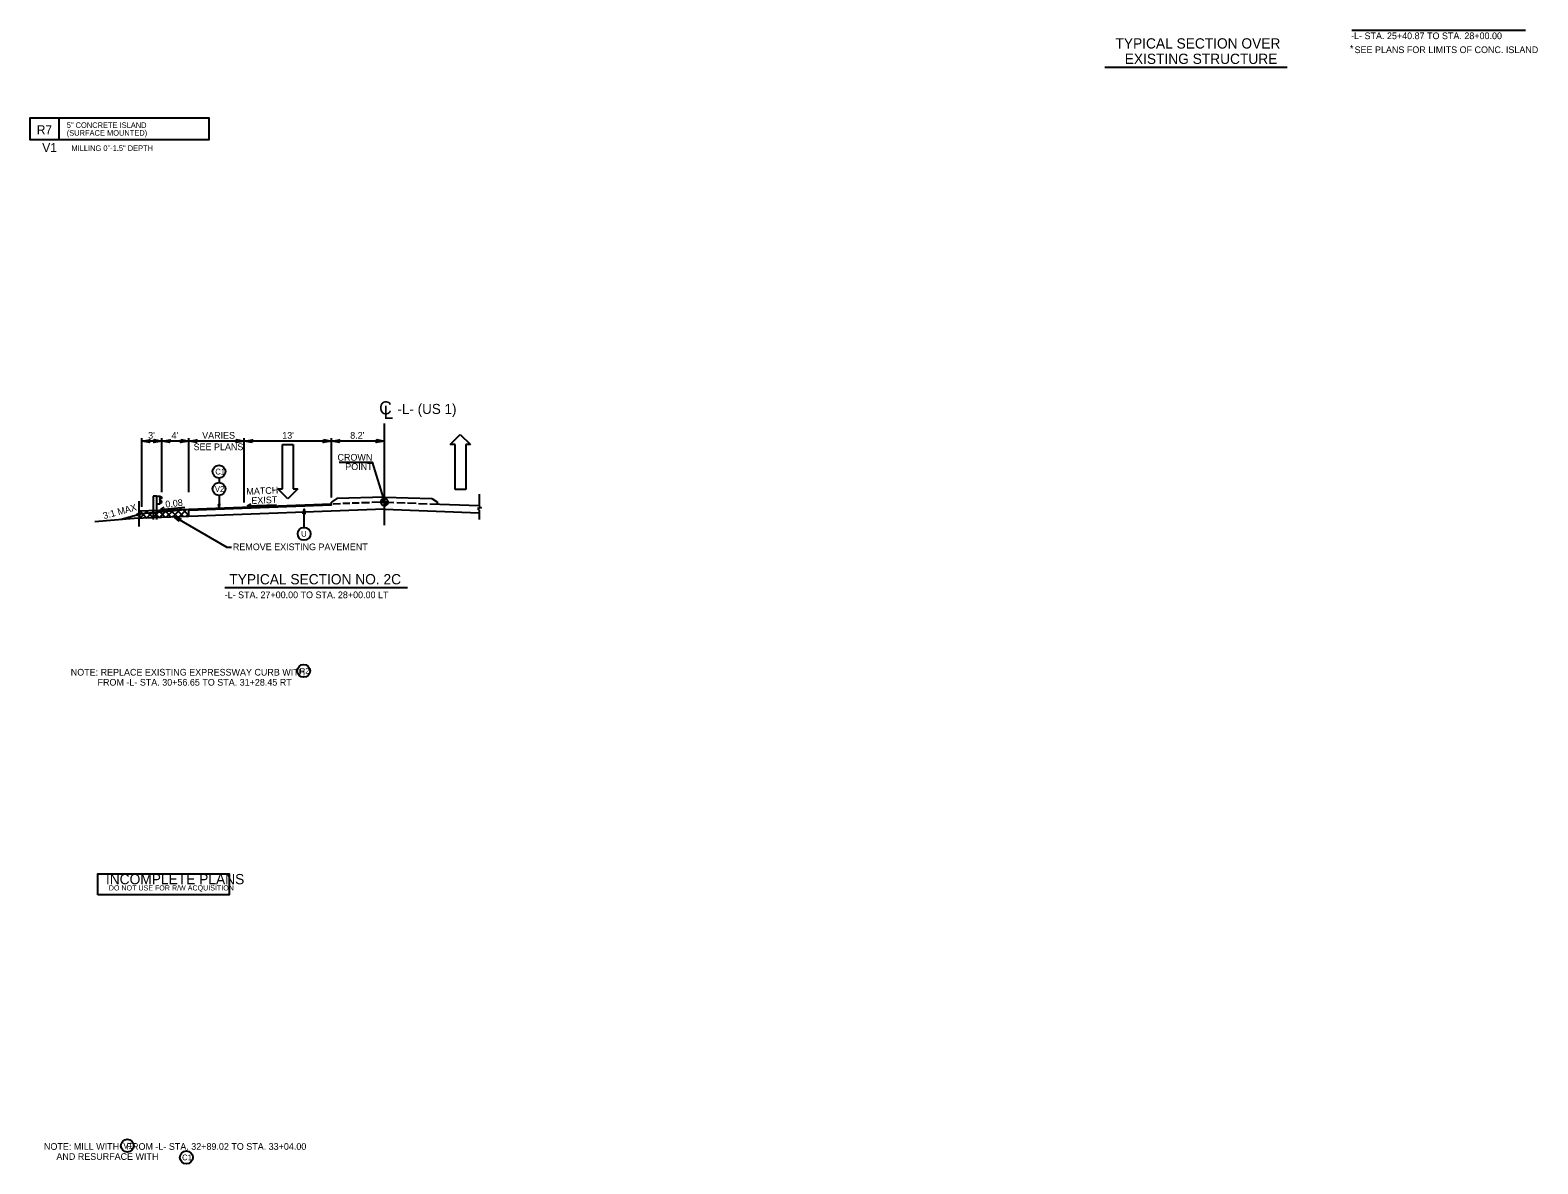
# Model space of a CAD drawing. Extents: x 573748 to 574632, y -54663 to -53209.
# Drawn here: x 574294.5 to 574632.1, y -53762.2 to -53508.3 of the extents above; entities that cross this region are included whole.
import ezdxf

# ---------------------------------------------------------------- set-up
doc = ezdxf.new("R2010")
doc.units = 0
for name, color, linetype in [('Prop Dimension', 7, 'Continuous'), ('Prop Dimension Text', 7, 'Continuous'), ('Prop Lane Arrow CELL', 7, 'Continuous'), ('Prop Pavement Schedule Description CELL', 7, 'Continuous'), ('Prop Terminator CELL', 7, 'Continuous'), ('Sheet Sticker Incomplete CELL', 7, 'Continuous'), ('Typical Arrow Superelevation CELL', 7, 'Continuous'), ('Typical Grade Point Symbol CELL', 7, 'Continuous'), ('Typical Guardrail CELL', 7, 'Continuous'), ('Typical Hinge Slope Arterial CELL', 7, 'Continuous'), ('Typical ID Circle CELL', 7, 'Continuous'), ('Typical Pavement Slope CELL', 7, 'Continuous'), ('Typical Terminator CELL', 7, 'Continuous'), ('Typical Text Centerline CELL', 7, 'Continuous'), ('Typical Text General CELL', 7, 'Continuous'), ('Typical Text ID Circle CELL', 7, 'Continuous'), ('Typical Text Label CELL', 7, 'Continuous')]:
    doc.layers.add(name, color=color, linetype=linetype)

# ---------------------------------------------------------------- blocks, each defined once
blk = doc.blocks.new('CENTERLINE TEXT CL')
at = {"layer": 'Typical Text Centerline CELL'}
blk.add_text('C', height=1.64, dxfattribs=at).set_placement((-0.55, -0.26))
blk.add_text('L', height=1.64, rotation=359.9469, dxfattribs=at).set_placement((0, -0.82))

msp = doc.modelspace()

# ---------------------------------------------------------------- linework, layer by layer
at = {"layer": 'Prop Dimension'}
for p, q in [((574373.79, -53619.22), (574373.79, -53596.43)), ((574319.46, -53615.1), (574319.46, -53599.67)), ((574323.96, -53611.82), (574323.96, -53599.67)), ((574329.96, -53611.82), (574329.96, -53599.67)), ((574342.41, -53614.12), (574342.41, -53599.67)), ((574361.91, -53613.02), (574361.91, -53599.67)), ((574323.96, -53600.37), (574319.46, -53600.37)), ((574329.96, -53600.37), (574323.96, -53600.37)), ((574342.41, -53600.37), (574329.96, -53600.37)), ((574361.91, -53600.37), (574342.41, -53600.37)), ((574373.79, -53600.37), (574361.91, -53600.37)), ((574363.15, -53613.25), (574361.91, -53614.06)), ((574373.79, -53612.91), (574363.15, -53613.25)), ((574373.79, -53612.91), (574384.42, -53613.25)), ((574384.42, -53613.25), (574385.67, -53614.06)), ((574395, -53612.21), (574395, -53614.98)), ((574318.76, -53616.59), (574318.26, -53616.89)), ((574318.26, -53616.89), (574319.12, -53617.09)), ((574318.76, -53613.82), (574318.76, -53616.59)), ((574329.96, -53615.66), (574318.76, -53616.08)), ((574318.76, -53616.49), (574319.2, -53616.06)), ((574319.03, -53617.65), (574320.66, -53616.01)), ((574319.09, -53616.07), (574320.61, -53617.59)), ((574320.45, -53616.02), (574321.97, -53617.54)), ((574320.49, -53617.59), (574322.13, -53615.95)), ((574321.82, -53615.96), (574323.34, -53617.49)), ((574321.96, -53617.54), (574323.6, -53615.9)), ((574323.18, -53615.91), (574324.7, -53617.43)), ((574323.43, -53617.48), (574325.07, -53615.84)), ((574324.54, -53615.86), (574326.06, -53617.38)), ((574324.9, -53617.43), (574326.54, -53615.79)), ((574325.91, -53615.81), (574327.43, -53617.33)), ((574326.37, -53617.37), (574328.01, -53615.73)), ((574327.27, -53615.76), (574328.79, -53617.28)), ((574327.84, -53617.32), (574329.48, -53615.68)), ((574328.63, -53615.71), (574329.96, -53617.04)), ((574329.31, -53617.26), (574329.96, -53616.61)), ((574361.91, -53614.72), (574329.96, -53615.92)), ((574373.79, -53615.6), (574329.96, -53617.24)), ((574329.96, -53617.24), (574329.96, -53615.66)), ((574361.91, -53614.72), (574361.91, -53614.06)), ((574363.94, -53614.39), (574362.34, -53614.45)), ((574366.04, -53614.31), (574364.44, -53614.37)), ((574368.14, -53614.23), (574366.54, -53614.29)), ((574370.44, -53614.15), (574368.64, -53614.21)), ((574373.79, -53614.02), (574370.95, -53614.13)), ((574373.79, -53614.02), (574375.88, -53614.1)), ((574373.79, -53615.6), (574395, -53616.39)), ((574376.54, -53614.12), (574378.43, -53614.19)), ((574378.97, -53614.21), (574380.91, -53614.29)), ((574381.45, -53614.31), (574383.39, -53614.38)), ((574383.93, -53614.4), (574395, -53614.81)), ((574385.67, -53614.46), (574385.67, -53614.06)), ((574395.51, -53615.28), (574394.64, -53615.47)), ((574394.64, -53615.47), (574395, -53615.82)), ((574395, -53614.98), (574395.51, -53615.28)), ((574395, -53615.82), (574395, -53617.88)), ((574317.73, -53617.7), (574308.94, -53618.44)), ((574329.96, -53617.24), (574317.73, -53617.7)), ((574319.12, -53617.09), (574318.76, -53617.44)), ((574318.76, -53617.44), (574318.76, -53619.49)), ((574318.91, -53617.3), (574319.25, -53617.64))]:
    msp.add_line(p, q, dxfattribs=at)
for points in [[(574363.67, -53605.11), (574371.08, -53605.11), (574373.79, -53614.02)], [(574339.56, -53624.16), (574338.54, -53624.16), (574326.45, -53617.14)]]:
    msp.add_lwpolyline(points, dxfattribs=at)
at = {"layer": 'Prop Lane Arrow CELL'}
for p, q in [((574388.54, -53601.13), (574390.78, -53598.86)), ((574390.78, -53598.86), (574393.08, -53601.13)), ((574350.98, -53611.08), (574350.98, -53601.1)), ((574350.98, -53601.1), (574353.33, -53601.1)), ((574353.33, -53601.1), (574353.33, -53611.08)), ((574389.62, -53601.13), (574388.54, -53601.13)), ((574389.62, -53611.21), (574389.62, -53601.13)), ((574393.08, -53601.13), (574392, -53601.13)), ((574392, -53601.13), (574392, -53611.21)), ((574352.19, -53613.32), (574349.91, -53611.08)), ((574349.91, -53611.08), (574350.98, -53611.08)), ((574354.4, -53611.08), (574352.19, -53613.32)), ((574353.33, -53611.08), (574354.4, -53611.08)), ((574392, -53611.21), (574389.62, -53611.21))]:
    msp.add_line(p, q, dxfattribs=at)
at = {"layer": 'Prop Pavement Schedule Description CELL'}
msp.add_lwpolyline([(574300.97, -53532.9), (574294.46, -53532.9), (574294.46, -53527.98), (574334.47, -53527.98), (574334.47, -53532.9), (574300.97, -53532.9), (574300.97, -53527.98)], dxfattribs=at)
at = {"layer": 'Prop Terminator CELL'}
for points in [[(574321.26, -53600.7), (574319.46, -53600.37), (574321.28, -53600.07), (574321.04, -53600.39)], [(574322.17, -53600.03), (574323.96, -53600.37), (574322.15, -53600.66), (574322.38, -53600.35)], [(574325.76, -53600.7), (574323.96, -53600.37), (574325.78, -53600.07), (574325.54, -53600.39)], [(574328.17, -53600.03), (574329.96, -53600.37), (574328.15, -53600.66), (574328.38, -53600.35)], [(574331.76, -53600.7), (574329.96, -53600.37), (574331.78, -53600.07), (574331.54, -53600.39)], [(574340.61, -53600.03), (574342.41, -53600.37), (574340.59, -53600.66), (574340.83, -53600.35)], [(574344.2, -53600.7), (574342.41, -53600.37), (574344.22, -53600.07), (574343.99, -53600.39)], [(574360.11, -53600.03), (574361.91, -53600.37), (574360.09, -53600.66), (574360.33, -53600.35)], [(574363.7, -53600.7), (574361.91, -53600.37), (574363.72, -53600.07), (574363.49, -53600.39)], [(574371.99, -53600.03), (574373.79, -53600.37), (574371.97, -53600.66), (574372.21, -53600.35)], [(574327.85, -53618.31), (574326.45, -53617.14), (574328.18, -53617.77), (574327.82, -53617.93)]]:
    msp.add_lwpolyline(points, close=True, dxfattribs=at)
at = {"layer": 'Sheet Sticker Incomplete CELL'}
msp.add_lwpolyline([(574309.63, -53701.94), (574309.63, -53697.24), (574339.03, -53697.24), (574339.03, -53701.94)], close=True, dxfattribs=at)
at = {"layer": 'Typical Arrow Superelevation CELL'}
for p, q in [((574323.71, -53615.7), (574329.08, -53615.15)), ((574323.71, -53615.7), (574324.45, -53615.16)), ((574343.07, -53614.89), (574343.85, -53614.4)), ((574343.07, -53614.89), (574349.59, -53614.61))]:
    msp.add_line(p, q, dxfattribs=at)
at = {"layer": 'Typical Grade Point Symbol CELL'}
for p, q in [((574373.79, -53614.02), (574373.79, -53613.21)), ((574372.98, -53614.02), (574373.79, -53614.02)), ((574373.79, -53614.83), (574373.79, -53614.02)), ((574374.59, -53614.02), (574373.79, -53614.02)), ((574373.79, -53614.02), (574373.79, -53614.83))]:
    msp.add_line(p, q, dxfattribs=at)
for points in [[(574373.09, -53613.62), (574373.09, -53614.02)], [(574373.1, -53613.6), (574373.1, -53614.02)], [(574373.12, -53613.57), (574373.12, -53614.02)], [(574373.14, -53613.55), (574373.14, -53614.02)], [(574373.15, -53613.53), (574373.15, -53614.02)], [(574373.17, -53613.51), (574373.17, -53614.02)], [(574373.18, -53613.49), (574373.18, -53614.02)], [(574373.2, -53613.47), (574373.2, -53614.02)], [(574373.22, -53613.45), (574373.22, -53614.02)], [(574373.23, -53613.44), (574373.23, -53614.02)], [(574373.25, -53613.42), (574373.25, -53614.02)], [(574373.27, -53613.41), (574373.27, -53614.02)], [(574373.28, -53613.39), (574373.28, -53614.02)], [(574373.3, -53613.38), (574373.3, -53614.02)], [(574373.31, -53613.37), (574373.31, -53614.02)], [(574373.33, -53613.36), (574373.33, -53614.02)], [(574373.35, -53613.35), (574373.35, -53614.02)], [(574373.36, -53613.34), (574373.36, -53614.02)], [(574373.38, -53613.33), (574373.38, -53614.02)], [(574373.39, -53613.32), (574373.39, -53614.02)], [(574373.41, -53613.31), (574373.41, -53614.02)], [(574373.43, -53613.3), (574373.43, -53614.02)], [(574373.44, -53613.29), (574373.44, -53614.02)], [(574373.46, -53613.29), (574373.46, -53614.02)], [(574373.47, -53613.28), (574373.47, -53614.02)], [(574373.49, -53613.27), (574373.49, -53614.02)], [(574373.51, -53613.26), (574373.51, -53614.02)], [(574373.52, -53613.26), (574373.52, -53614.02)], [(574373.54, -53613.25), (574373.54, -53614.02)], [(574373.56, -53613.25), (574373.56, -53614.02)], [(574373.57, -53613.24), (574373.57, -53614.02)], [(574373.59, -53613.24), (574373.59, -53614.02)], [(574373.6, -53613.24), (574373.6, -53614.02)], [(574373.62, -53613.23), (574373.62, -53614.02)], [(574373.64, -53613.23), (574373.64, -53614.02)], [(574373.65, -53613.23), (574373.65, -53614.02)], [(574373.67, -53613.22), (574373.67, -53614.02)], [(574373.68, -53613.22), (574373.68, -53614.02)], [(574373.7, -53613.22), (574373.7, -53614.02)], [(574373.72, -53613.22), (574373.72, -53614.02)], [(574373.73, -53613.22), (574373.73, -53614.02)], [(574373.75, -53613.22), (574373.75, -53614.02)], [(574373.76, -53613.21), (574373.76, -53614.02)], [(574373.78, -53613.21), (574373.78, -53613.21), (574373.78, -53614.02)], [(574372.99, -53613.91), (574372.99, -53614.02)], [(574373.01, -53613.82), (574373.01, -53614.02)], [(574373.02, -53613.77), (574373.02, -53614.02)], [(574373.04, -53613.72), (574373.04, -53614.02)], [(574373.06, -53613.69), (574373.06, -53614.02)], [(574373.07, -53613.65), (574373.07, -53614.02)], [(574373.8, -53614.02), (574373.8, -53614.83), (574373.8, -53614.83)], [(574373.82, -53614.02), (574373.82, -53614.83)], [(574373.83, -53614.02), (574373.83, -53614.82)], [(574373.85, -53614.02), (574373.85, -53614.82)], [(574373.86, -53614.02), (574373.86, -53614.82)], [(574373.88, -53614.02), (574373.88, -53614.82)], [(574373.9, -53614.02), (574373.9, -53614.82)], [(574373.91, -53614.02), (574373.91, -53614.81)], [(574373.93, -53614.02), (574373.93, -53614.81)], [(574373.95, -53614.02), (574373.95, -53614.81)], [(574373.96, -53614.02), (574373.96, -53614.81)], [(574373.98, -53614.02), (574373.98, -53614.8)], [(574373.99, -53614.02), (574373.99, -53614.8)], [(574374.01, -53614.02), (574374.01, -53614.79)], [(574374.03, -53614.02), (574374.03, -53614.79)], [(574374.04, -53614.02), (574374.04, -53614.78)], [(574374.06, -53614.02), (574374.06, -53614.78)], [(574374.07, -53614.02), (574374.07, -53614.77)], [(574374.09, -53614.02), (574374.09, -53614.77)], [(574374.11, -53614.02), (574374.11, -53614.76)], [(574374.12, -53614.02), (574374.12, -53614.75)], [(574374.14, -53614.02), (574374.14, -53614.75)], [(574374.15, -53614.02), (574374.15, -53614.74)], [(574374.17, -53614.02), (574374.17, -53614.73)], [(574374.19, -53614.02), (574374.19, -53614.72)], [(574374.2, -53614.02), (574374.2, -53614.71)], [(574374.22, -53614.02), (574374.22, -53614.7)], [(574374.24, -53614.02), (574374.24, -53614.69)], [(574374.25, -53614.02), (574374.25, -53614.68)], [(574374.27, -53614.02), (574374.27, -53614.67)], [(574374.28, -53614.02), (574374.28, -53614.66)], [(574374.3, -53614.02), (574374.3, -53614.64)], [(574374.32, -53614.02), (574374.32, -53614.63)], [(574374.33, -53614.02), (574374.33, -53614.61)], [(574374.35, -53614.02), (574374.35, -53614.6)], [(574374.36, -53614.02), (574374.36, -53614.58)], [(574374.38, -53614.02), (574374.38, -53614.57)], [(574374.4, -53614.02), (574374.4, -53614.55)], [(574374.41, -53614.02), (574374.41, -53614.53)], [(574374.43, -53614.02), (574374.43, -53614.51)], [(574374.44, -53614.02), (574374.44, -53614.49)], [(574374.46, -53614.02), (574374.46, -53614.46)], [(574374.48, -53614.02), (574374.48, -53614.44)], [(574374.49, -53614.02), (574374.49, -53614.41)], [(574374.51, -53614.02), (574374.51, -53614.38)], [(574374.53, -53614.02), (574374.53, -53614.35)], [(574374.54, -53614.02), (574374.54, -53614.31)], [(574374.56, -53614.02), (574374.56, -53614.26)], [(574374.57, -53614.02), (574374.57, -53614.2)], [(574374.59, -53614.02), (574374.59, -53614.11)]]:
    msp.add_lwpolyline(points, dxfattribs=at)
msp.add_circle((574373.79, -53614.02), 0.806, dxfattribs=at)
for start, end in [(90.0095, 180.0095), (270.0095, 0.0095)]:
    msp.add_arc((574373.79, -53614.02), 0.806, start, end, dxfattribs=at)
at = {"layer": 'Typical Guardrail CELL'}
for p, q in [((574322.73, -53612.66), (574321.99, -53612.66)), ((574321.99, -53612.66), (574321.99, -53616.39)), ((574322.73, -53612.66), (574322.73, -53616.39)), ((574322.73, -53612.66), (574323.48, -53612.66)), ((574323.48, -53612.66), (574323.48, -53614.4)), ((574323.48, -53612.66), (574323.91, -53612.97)), ((574323.48, -53613.46), (574323.91, -53613.16)), ((574323.48, -53613.53), (574323.48, -53613.46)), ((574323.48, -53613.53), (574323.48, -53613.6)), ((574323.48, -53613.6), (574323.91, -53613.91)), ((574322.73, -53616.39), (574321.99, -53616.39)), ((574321.99, -53616.39), (574321.99, -53617.9)), ((574322.73, -53614.4), (574323.48, -53614.4)), ((574322.73, -53616.39), (574322.73, -53617.9)), ((574323.48, -53614.4), (574323.91, -53614.1))]:
    msp.add_line(p, q, dxfattribs=at)
for centre, start, end in [((574323.85, -53613.06), 304.9888, 54.997), ((574323.85, -53614), 304.9634, 54.9941)]:
    msp.add_arc(centre, 0.116, start, end, dxfattribs=at)
at = {"layer": 'Typical Hinge Slope Arterial CELL'}
msp.add_line((574319.46, -53616.68), (574314.85, -53617.94), dxfattribs=at)
at = {"layer": 'Typical ID Circle CELL'}
for p, q in [((574336.75, -53608.64), (574336.75, -53609.64)), ((574336.75, -53612.53), (574336.75, -53615.51)), ((574355.81, -53619.68), (574355.81, -53615.6))]:
    msp.add_line(p, q, dxfattribs=at)
for centre in [(574336.75, -53607.19), (574336.75, -53611.08), (574355.81, -53621.12), (574355.7, -53651.82), (574316.21, -53758.15), (574329.45, -53760.77)]:
    msp.add_circle(centre, 1.44, dxfattribs=at)
at = {"layer": 'Typical Pavement Slope CELL'}
for p, q in [((574329.96, -53615.66), (574319.46, -53616.68)), ((574361.91, -53614.46), (574329.96, -53615.66))]:
    msp.add_line(p, q, dxfattribs=at)
at = {"layer": 'Typical Terminator CELL'}
for points in [[(574336.57, -53614.46), (574336.75, -53615.51), (574336.94, -53614.45), (574336.75, -53614.59)], [(574355.63, -53616.65), (574355.81, -53615.6), (574356, -53616.66), (574355.81, -53616.52)]]:
    msp.add_lwpolyline(points, close=True, dxfattribs=at)
at = {"layer": 'Typical Text General CELL'}
msp.add_line((574590.42, -53508.33), (574629.3, -53508.33), dxfattribs=at)
at = {"layer": 'Typical Text Label CELL'}
for p, q in [((574535.13, -53516.62), (574575.97, -53516.62)), ((574338.07, -53633.16), (574378.92, -53633.16))]:
    msp.add_line(p, q, dxfattribs=at)

# ---------------------------------------------------------------- block references
at = {"layer": 'Prop Dimension', "xscale": 1.8000000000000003, "yscale": 1.8000000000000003}
msp.add_blockref('CENTERLINE TEXT CL', (574373.59, -53593.92), dxfattribs=at)

# ---------------------------------------------------------------- texts
at = {"layer": 'Prop Dimension'}
msp.add_text('REMOVE EXISTING PAVEMENT', height=1.5, rotation=360, dxfattribs=at).set_placement((574339.85, -53624.79))
at = {"layer": 'Prop Dimension Text'}
for s, height, p in [('TYPICAL SECTION OVER', 2.3, (574537.5, -53512.45)), ('*', 1.5, (574590, -53513.18)), ('EXISTING STRUCTURE', 2.3, (574539.57, -53515.9)), ('-L- (US 1)', 2.25, (574376.72, -53594.28)), ("3'", 1.5, (574320.88, -53599.81)), ("4'", 1.5, (574326.13, -53599.82)), ('VARIES', 1.5, (574332.98, -53599.82)), ("13'", 1.5, (574350.91, -53599.82)), ("8.2'", 1.5, (574366.13, -53599.82)), ('SEE PLANS', 1.5, (574331.06, -53602.39)), ('CROWN', 1.5, (574363.28, -53604.74)), ('POINT', 1.5, (574365.02, -53606.84)), ('TYPICAL SECTION NO. 2C', 2.3, (574339.06, -53632.44))]:
    msp.add_text(s, height=height, dxfattribs=at).set_placement(p)
for s, rotation, p in [('0.08', 5.7688, (574324.81, -53615.24)), ('MATCH', 2.4521, (574342.91, -53612.39)), ('EXIST', 2.4521, (574344.03, -53614.45)), ('3:1 MAX', 15.3306, (574311.01, -53617.85))]:
    msp.add_text(s, height=1.5, rotation=rotation, dxfattribs=at).set_placement(p)
at = {"layer": 'Prop Pavement Schedule Description CELL'}
for s, height, p in [('5" CONCRETE ISLAND', 1.25, (574302.65, -53530.23)), ('R7', 2, (574295.95, -53531.64)), ('(SURFACE MOUNTED)', 1.25, (574302.65, -53531.97)), ('V1', 2, (574297.17, -53535.64)), ('MILLING 0"-1.5" DEPTH', 1.25, (574303.7, -53535.39))]:
    msp.add_text(s, height=height, dxfattribs=at).set_placement(p)
at = {"layer": 'Sheet Sticker Incomplete CELL'}
for s, height, p in [('INCOMPLETE PLANS', 2.304, (574311.42, -53699.6)), ('DO NOT USE FOR R/W ACQUISITION', 1.152, (574312.07, -53700.99))]:
    msp.add_text(s, height=height, dxfattribs=at).set_placement(p)
at = {"layer": 'Typical Text General CELL'}
for s, p in [('-L- STA. 25+40.87 TO STA. 28+00.00', (574590.26, -53510.35)), ('SEE PLANS FOR LIMITS OF CONC. ISLAND', (574591.04, -53513.47)), ('-L- STA. 27+00.00 TO STA. 28+00.00 LT', (574338.01, -53635.54)), ('NOTE: REPLACE EXISTING EXPRESSWAY CURB WITH ', (574303.55, -53652.87)), ('FROM -L- STA. 30+56.65 TO STA. 31+28.45 RT', (574309.55, -53655.12)), ('NOTE: MILL WITH   FROM -L- STA. 32+89.02 TO STA. 33+04.00', (574297.55, -53759.07)), ('     AND RESURFACE WITH', (574297.55, -53761.32))]:
    msp.add_text(s, height=1.5, dxfattribs=at).set_placement(p)
at = {"layer": 'Typical Text ID Circle CELL'}
for s, height, p in [('C1', 1.291, (574335.92, -53607.84)), ('V2', 1.291, (574335.82, -53611.73)), ('U', 1.29, (574355.14, -53621.77)), ('R2', 1.291, (574354.81, -53652.46)), ('V1', 1.291, (574315.32, -53758.79)), ('C1', 1.291, (574328.47, -53761.41))]:
    msp.add_text(s, height=height, dxfattribs=at).set_placement(p)

doc.saveas('drawing.dxf')
